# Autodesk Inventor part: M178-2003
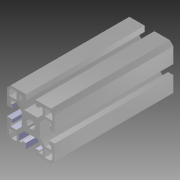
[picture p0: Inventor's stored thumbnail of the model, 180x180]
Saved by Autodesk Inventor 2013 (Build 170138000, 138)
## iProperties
Created: 2004-10
Material: Aluminium - 6061
Document SubType Name: Modeling
Designer: Autodesk, Inc.
Manufacturer: Standard
Standards Organization: Custom
Description: PC RACK, FRONT/BACK BAR
Stock Number: 10-540
Catalog Web Link: http://www.parker.com/ead/cm1.asp?cmid=809
Vendor: PARKER IPS
Part Number: M178-2003
Mass: 179.948 g
Surface Area: 483.565 cm^2
Volume: 66.4013 cm^3
Density: 2.71 g/cm^3
CAGE: 1LJX3
Dept. ID: Product Design
Description #2: ---
Finish #1: ---
Finish #2: ---
Material ID: ---
Project Number: ---
Stock Number: 10-040
Length: 562.600 mm
Author: Autodesk, Inc.
Revision Number: A
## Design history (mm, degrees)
derived "40 Series Profiles.ipt"
sketch "Sketch1"
  geometry: L1 (-24, 0)-(-21, 0) reference; L2 (-21, 0)-(-8, 0) reference; L3 (1.625, 0)-(-9.625, 0) reference; L4 (0, 0)-(13, 0) reference; L5 (13, 0)-(16, 0) reference; L6 (16, 562.6)-(16, 0) reference; L7 (-24, 0)-(16, 40)
  constraints: 2 end point, 1 point on line
  dimensions: "d0" = 45 deg angle of L6 L7
extrude "Extrusion1" cut sketch "Sketch1" stored distance "d1" = 10; taper "d2" = 0 deg
sketch "Sketch3"
  geometry: L1 (17, 112.52)-(17, -675.12) reference; L2 (11.375, -548.225)-(22.625, -536.975) reference; 2 further points
  constraints: 1 midpoint, 1 point on line
  dimensions: "d19" = 23.4 distance of point (17, -519.2) point (17, -542.6)
hole "Hole2" sketch "Sketch3" diameter "d12" = 4.917; stored, may be unused: countersink angle "d16" = 90 deg, drill point angle "d18" = 118 deg; dims "d13" = 6, "d14" = 4, "d15" = 2, "d17" = 8
mirror "Mirror1"
body "Solid1"
tag "TaggingFeature2"
feature "Solid1::40 Series Profiles.ipt" dims "ScaleForDerivedMember" = 10
other parameters: "Length" = 562.6
